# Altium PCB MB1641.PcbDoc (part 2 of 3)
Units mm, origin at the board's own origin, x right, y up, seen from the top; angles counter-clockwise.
Board outline 70 x 64.48 mm, 4 copper layers (Top Layer, GND, VCC, Bottom Layer), stack 1.502 mm thick; 161 components, 126 nets, 622 pads, 1092 vias.
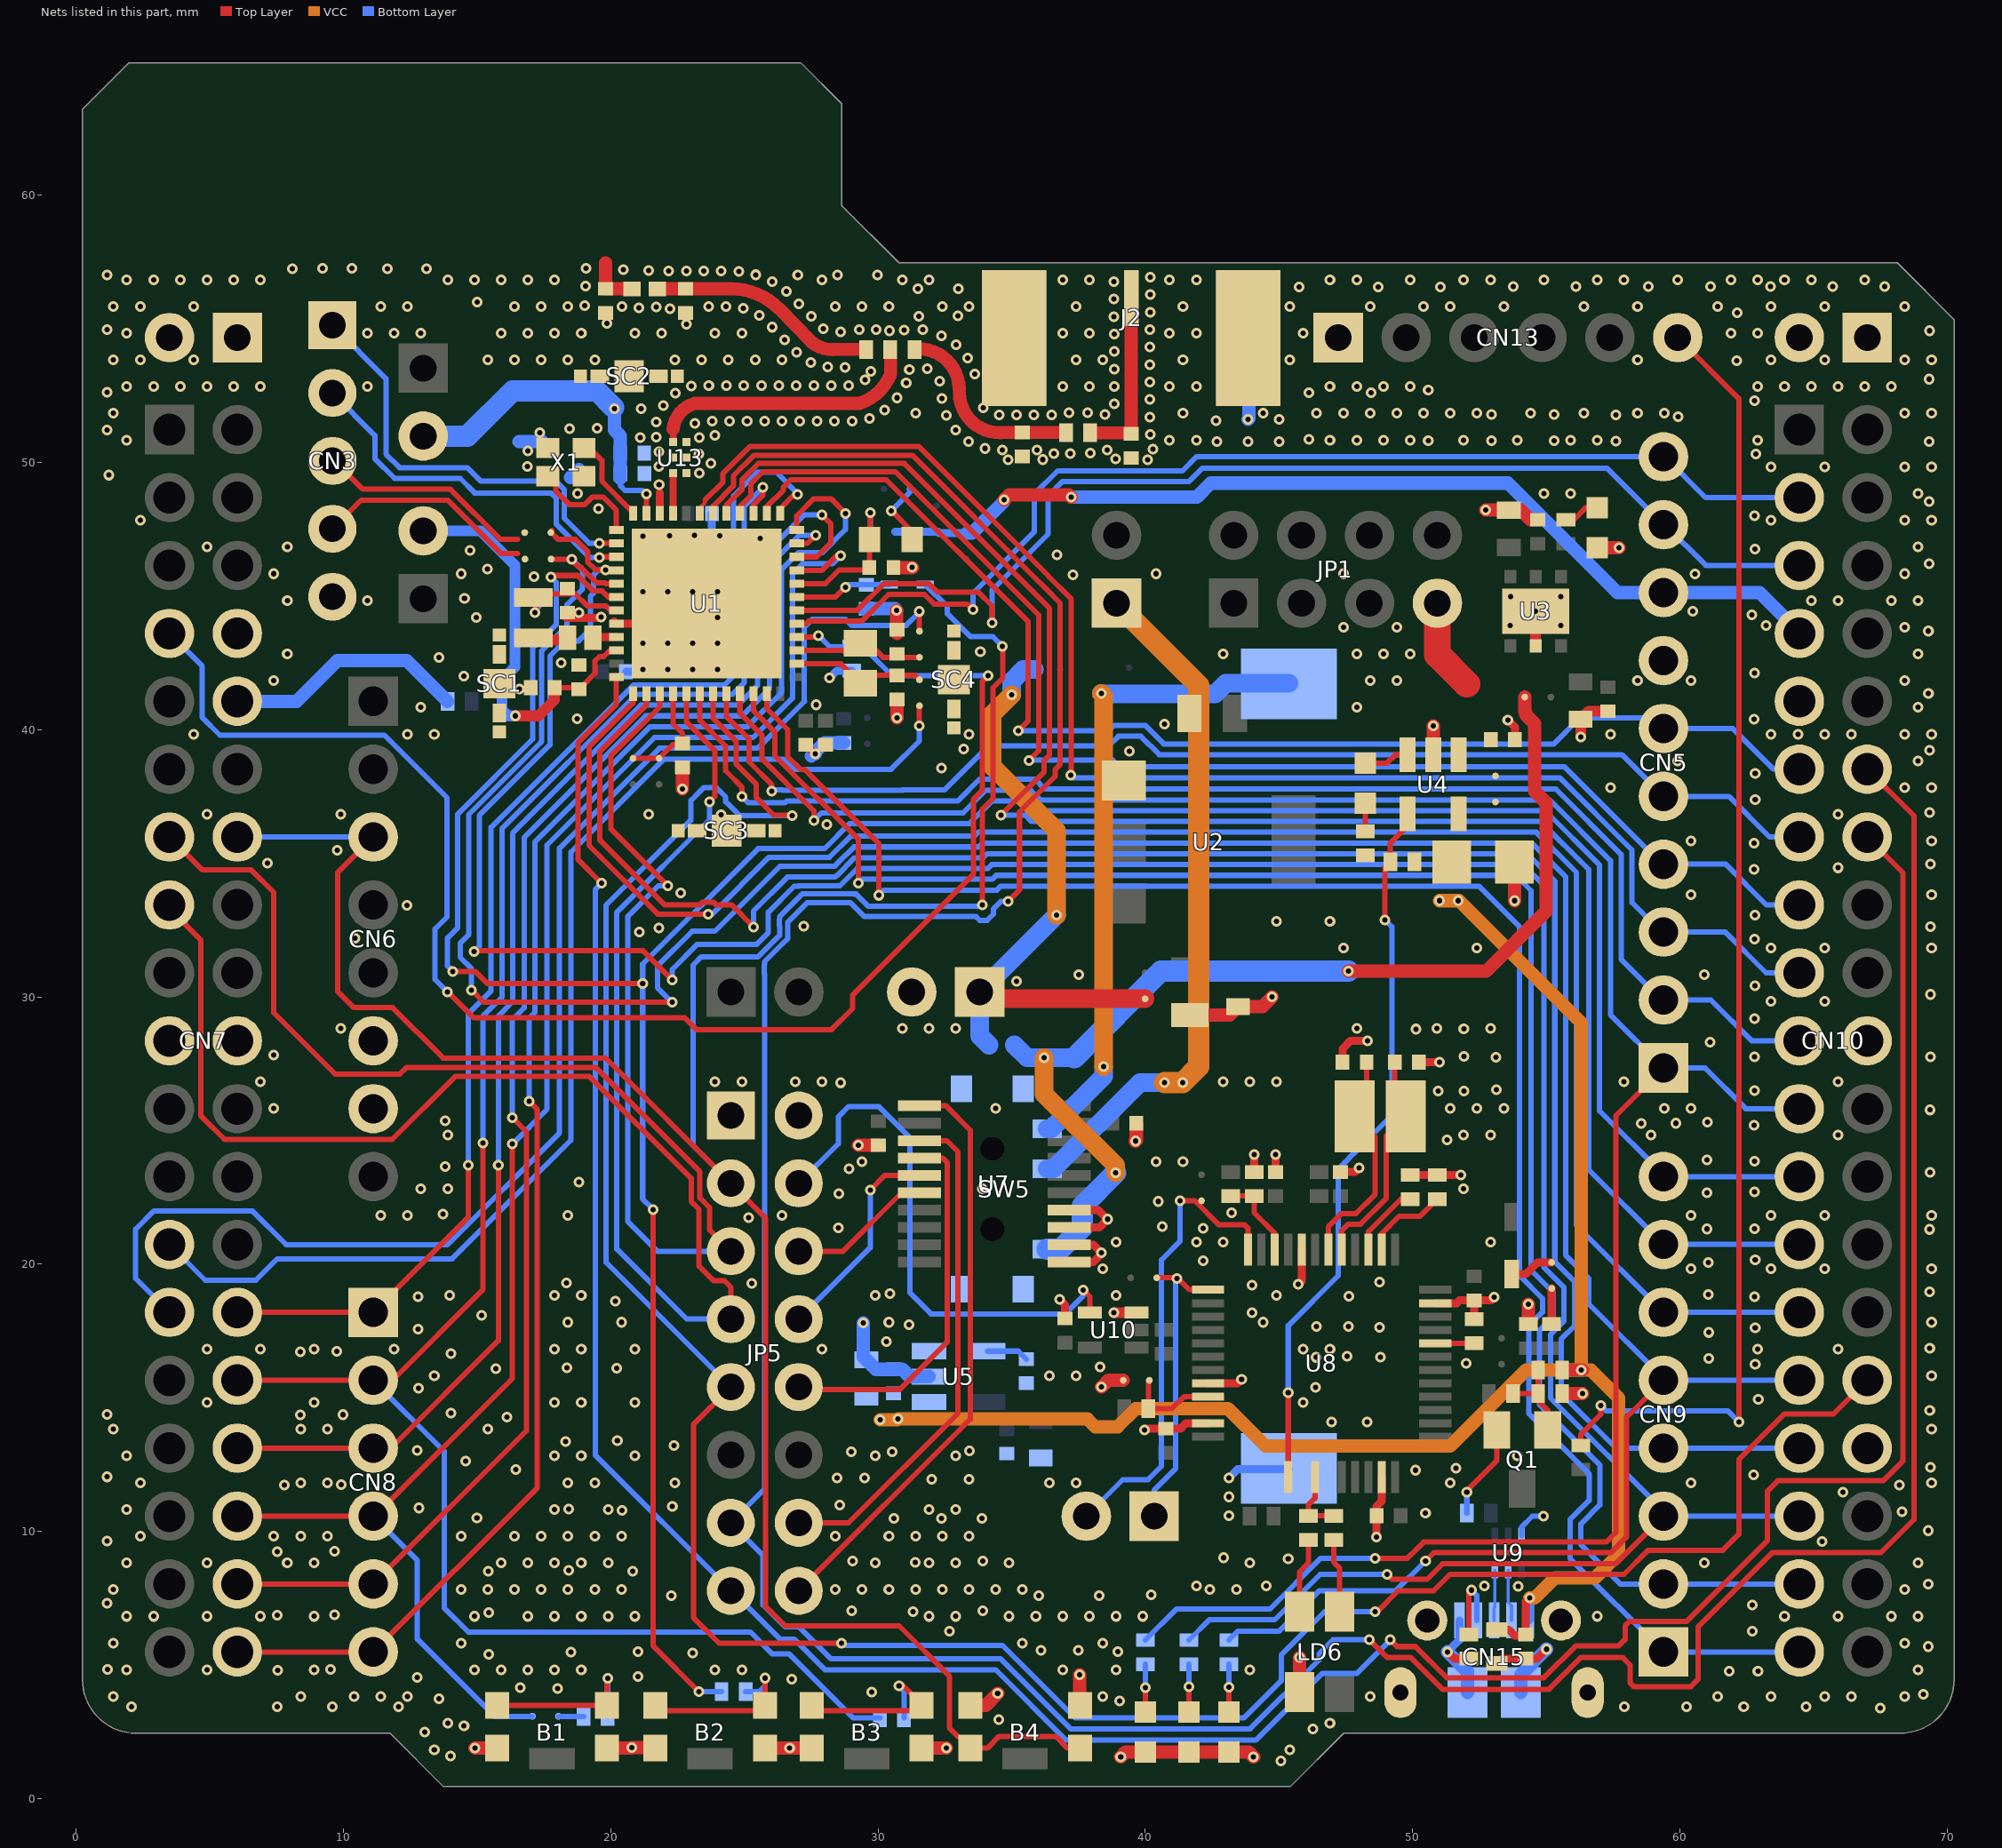
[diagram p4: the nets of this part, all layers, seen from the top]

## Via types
v1: diameter 0.4, hole 0.2, Top Layer to Bottom Layer, tented both sides, 1003 vias
v2: diameter 0.4/0.4/0.3/0.4 (per signal layer), hole 0.2, Top Layer to Bottom Layer, tented both sides, 89 vias

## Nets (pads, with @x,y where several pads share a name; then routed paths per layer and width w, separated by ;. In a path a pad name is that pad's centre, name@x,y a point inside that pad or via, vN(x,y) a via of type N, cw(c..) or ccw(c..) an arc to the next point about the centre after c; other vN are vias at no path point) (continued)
5V_USB_STLINK: C11.1 C21.2 C25.2 C51.1 CN15.1 R11.2 R12.2 R16.2 SB15.1 U4.5 U5.1 U5.3 U12.1 | length 64.5
  Top Layer w0.3: U12.1@53.15,6.325 53.6,6.325 53.825,6.1 54.18,6.1 C51.1@54.23,6.15 54.23,7.391 54.252,7.391 v1(54.381,7.521)
  Top Layer w0.5: R16.2@55.59,16.044 v1(56.3,16.044) v1@56.347,16.044
  VCC w0.5: v1(30.087,14.19) 30.733,14.19 v1(30.752,14.209) 37.834,14.209 38.12,13.923 38.967,13.923 39.644,14.6 43.095,14.6 44.495,13.2 51.4,13.2 54.244,16.044 v1(56.3,16.044) ; v1(51,33.6) v1(51.7,33.6) 51.733,33.6 56.3,29.033 v1(56.3,16.044) ; v1(54.381,7.521) 54.564,7.521 55.315,8.271 56.822,8.271 57.707,9.157 57.707,15 56.663,16.044 v1(56.3,16.044)
  Bottom Layer w0.3: CN15.1@54.345,6.675 54.381,6.711 v1(54.381,7.521)
AIN_1: R26.2 R28.2 U8.10 | length 3.2
  Top Layer w0.2: R26.2@43.2,22.55 R28.2@44.07,22.55 44.07,21.927 44.845,21.152 U8.10@44.845,20.544
ANT: C37.2 L1.2 | length 2
  Top Layer w0.49: 19.816,57.466 C37.2@19.816,56.488 L1.2@20.8,56.488
AT0: CN3.1 U1.26 | length 16.3
  Top Layer w0.2: v1@19.595,46.962 U1.26@20.214,46.962
  Bottom Layer w0.2: CN3.1@9.596,55.131 11.6,53.127 11.6,50.306 12.109,49.798 14.639,49.798 15.139,49.297 17.947,49.297 18.273,48.972 18.273,47.898 19.198,46.973 v1(19.583,46.973)
AT1: CN3.2 U1.27 | length 14.2
  Top Layer w0.2: v1@19.595,46.462 U1.27@20.214,46.462
  Bottom Layer w0.2: CN3.2@9.596,52.591 11.184,51.003 11.184,50.134 11.924,49.394 14.378,49.394 14.919,48.853 17.766,48.853 17.971,48.648 17.971,47.773 17.973,47.772 17.973,47.681 19.222,46.431 v1(19.583,46.431)
AT2: CN3.3 SB5.2 | length 8.1
  Top Layer w0.2: CN3.3@9.596,50.051 9.676,50.051 10.736,48.991 14.009,48.991 15.883,47.117 16.521,47.117
AT3: CN3.4 SB6.2 | length 8.2
  Top Layer w0.2: CN3.4@9.596,47.511 10.673,48.588 13.908,48.588 15.912,46.584 16.519,46.584
AVDD: CN5.8 CN10.7 SB25.1 SB26.1 SB27.1 | length 37
  Top Layer w0.5: v1(34.72,48.6) 34.894,48.774 37.146,48.774 v1(37.22,48.7)
  Bottom Layer w0.3: SB25.1@30.65,47.4 SB27.1@32.2,47.4 32.245,47.4 32.295,47.35 SB26.1@33.32,47.35
  Bottom Layer w0.5: SB26.1@33.32,47.35 33.525,47.35 v1@34.725,48.55 ; v1(37.22,48.7) 41.926,48.7 42.446,49.22 53.561,49.22 57.657,45.124 CN5.8@59.38,45.124 62.976,45.124 64.46,43.64 CN10.7@64.46,43.6
BOOT0: CN7.7 R6.2 U1.4 | length 60.1
  Top Layer w0.2: v1@13.91,30.19 14.874,29.226 22.768,29.226 23.216,28.778 28.266,28.778 29.058,29.57 29.058,30.074 33.579,34.595 33.579,37.401 33.9,37.722 33.9,41.796 v1(34.12,42.016) ; U1.4@26.964,43.462 27.699,43.462 v1@27.775,43.538
  Bottom Layer w0.2: CN7.7@3.5,43.6 4.73,42.37 4.73,40.45 5.39,39.79 11.542,39.79 13.88,37.452 13.88,32.99 13.43,32.54 13.43,30.654 v1(13.904,30.18) ; v1(27.775,43.516) 28.188,43.103 R6.2@29.018,43.103 29.44,43.103 30.528,42.016 v1(34.12,42.016)
GND: B1.1 B1.3 B2.1 B2.3 B3.1 B3.3 B4.2 B4.4 C3.1 C6.1 C7.1 C8.1 C9.2 C10.2 C11.2 C12.1 C13.1 C14.1 C15.1 C16.1 C17.1 C18.1 C19.1 C20.1 C21.1 C22.1 C23.1 C24.1 C25.1 C26.1 C27.1 C28.2 C29.1 C31.1 C32.1 C33.1 C34.1 C36.1 C37.1 C39.1 C40.1 C41.2 C42.1 C43.2 C44.2 C45.2 C46.1 C47.1 C48.1 C49.1 C50.1 C51.2 CN2.2 CN3.5 CN4.2 CN5.7 CN6.6 CN6.7 CN7.8 CN7.19 CN7.20 CN10.9 CN10.20 CN10.32 CN11.1 CN11.2 CN12.1 CN12.2 CN13.1 CN15.5 CN15.6 CN15.7 CN15.8 CN15.9 CN15.10 CN15.11 J2.2 J2.3 J2.4 J2.5 JP5.1 JP5.2 LD1.2 LD2.2 LD3.2 LD5.2 LD6.1 R6.1 R15.2 R18.2 R19.2 R20.1 R22.2 R23.1 R28.1 SB32.2 SC1.1 SC2.1 SC3.1 SC4.1 SW5.0 U1.22 U1.32 U1.49 U2.1 U3.2 U3.EP U4.2 U5.2 U7.11 U7.12 U7.13 U7.14 U8.8 U8.20 U8.23 U8.35 U8.47 U9.3 U10.3 U12.2 U13.A2 U13.B1 U13.B2 U13.B3 X1.2 X1.4 | length 90.3
  Top Layer w0.3: C29.1@18.351,44.175 v1@19.621,44.175 ; U1.32@20.132,44.044 U1.32@20.214,43.962 22.839,43.962 U1.49@23.589,44.712 ; U1.22@21.839,48.087 21.839,48.853 ; C20.1@27.289,39.435 C20.1@27.3,39.435 27.307,39.428 v1(27.649,39.085) ; v1(36.791,18.68) 37,18.471 C43.2@37,17.97 ; U7.11@37.152,20.075 38.045,20.075 38.379,20.409 v1(38.362,20.425) 38.062,20.725 U7.12@37.152,20.725 ; U7.13@37.152,21.375 38.275,21.375 v1(38.586,21.686) 38.246,22.025 U7.14@37.152,22.025 ; v1(39.97,13.8) 40.02,13.85 C48.1@40.77,13.85 41.32,13.85 41.514,14.044 U8.23@42.345,14.044 ; U8.20@42.345,15.544 43.444,15.544 v1(43.6,15.7) ; R28.1@44.07,23.45 v1(44.07,24.1) ; C50.1@44.87,23.45 v1(44.87,24.1) ; v1(45.72,19.247) 45.845,19.372 U8.8@45.845,20.544 ; C46.1@47.3,23.45 47.845,23.45 v1(47.995,23.6) ; C44.2@47.377,27.561 47.377,28.057 47.68,28.36 v1(48.314,28.36) ; v1@48.65,9.805 C47.1@48.65,10.591 48.65,10.95 48.845,11.145 U8.35@48.845,12.044 ; R22.2@49.913,23.337 R18.2@50.913,23.337 v1(51.801,23.337) ; C45.2@50.231,27.561 v1(50.998,27.561) ; U8.47@50.845,18.544 51.644,18.544 51.75,18.65 C49.1@52.3,18.65 ; v1(51.3,5.5) 51.55,5.25 R23.1@52.1,5.25 ; R19.2@52.294,17.95 52.3,17.956 C49.1@52.3,18.65 ; v1(53.05,18.769) 52.931,18.65 C49.1@52.3,18.65 ; U12.2@53.15,5.075 53.325,5.25 C51.2@54.23,5.25 54.65,5.25 v1(55,5.6) ; v1(53.554,40.362) 53.823,40.093 C12.1@53.823,39.629
  Top Layer w0.4: v1(38.83,18.19) U10.3@39.675,18.19 ; U3.2@54.6,43.13 v1(54.6,44.43) ; v1(56.28,39.72) C13.1@56.28,40.385 56.58,40.685 C16.1@57.296,40.685
  Top Layer w0.5: v1(14.931,1.9) B1.1@15.76,1.9 ; B1.3@19.86,1.9 20.78,1.9 v1(20.793,1.913) B2.1@21.622,1.913 ; v1(22.687,37.777) 22.687,38.581 C31.1@22.689,38.583 ; B2.3@25.773,1.9 v1(26.7,1.9) B3.1@27.528,1.9 ; v1(29.262,24.45) C42.1@30.012,24.45 ; C32.1@30.579,46.062 v1@31.288,46.062 ; v1(30.7,44.462) 30.7,43.612 C7.1@30.712,43.6 ; v1(30.712,40.441) C6.1@30.712,41.128 ; B3.3@31.629,1.9 v1(32.557,1.9) ; B4.2@33.454,3.3 B4.2@33.46,3.306 ; B4.2@33.454,3.5 34.035,3.5 v1(34.477,3.943) ; v1(37.55,4.638) 37.55,3.744 37.56,3.734 37.554,3.728 B4.4@37.554,3.5 ; v1(38.362,15.407) 38.615,15.66 SB32.2@39.175,15.66 ; C9.2@41.67,29.327 43.158,29.327 C8.1@43.47,29.639 44.384,29.639 v1(44.745,30) ; LD6.1@45.77,4 v1(45.77,5.3) ; U4.2@50.764,39.054 v1(50.764,40.136) ; v1(52.736,48.211) C15.1@53.6,48.211 54.039,48.211 54.4,47.85 C14.1@54.672,47.85 ; v1(53.805,33.6) C11.2@53.805,35.048 ; R15.2@54.326,17.759 v1(54.326,18.499) ; R20.1@55.59,15.159 v1(56.347,15.159) ; LD5.2@56.9,46.8 v1(57.717,46.8)
  Top Layer w0.508: v1(39.08,1.57) 39.26,1.75 LD1.2@40.004,1.75 LD2.2@41.631,1.75 LD3.2@43.124,1.75 43.868,1.75 v1(44.048,1.57) ; v1(39.63,24.61) 39.662,24.642 C41.2@39.662,25.275
  Bottom Layer w0.2: U9.3@54.074,9.85 54.074,10.174 54.476,10.576 v1(54.898,10.576)
  Bottom Layer w0.3: C18.1@20.586,42.164 21.128,42.164 v1(21.214,42.25) ; C19.1@23.789,48.087 23.789,47.31 v1@24.011,47.088 ; v1(28.192,41.928) 28.467,42.203 R6.1@29.018,42.203 ; v1(43.12,12) 43.454,12.334 CN2.2@45.37,12.334 ; v1(51.3,5.5) 51.745,5.945 CN15.5@51.745,6.675
  Bottom Layer w0.5: 16.578,50.775 17.45,50.775 ; 18.5,49.425 18.808,49.733 18.859,49.682 ; v1(27.649,39.085) 27.581,39.085 27.51,39.014 27.998,39.503 C28.2@28.718,39.503 ; C3.1@29.525,44.483 C3.1@29.562,44.521 30.641,44.521 v1(30.7,44.462) ; v1(43.845,51.6) 43.881,51.636 J2.5@43.881,54.86 ; v1(51.3,5.5) 52.045,4.755 CN15.11@52.045,3.975 ; CN15.10@54.045,3.975 54.045,4.645 v1(55,5.6)
  Bottom Layer w0.508: v1(29.452,17.799) 29.452,16.537 C21.1@29.562,16.427 29.917,16.072 C25.1@30.579,16.072 30.908,16.072 31.18,15.8 U5.2@31.91,15.8
  other v1: 45.068,1.417 14.015,1.61 13.407,1.83 45.407,1.83 13.052,2.507 46.271,2.622 14.52,2.738 13.907,2.83 46.907,2.83 34.512,2.96 67.493,3.391 7.531,3.441 9.594,3.441 57.909,3.441 60.243,3.441 62.378,3.441 64.712,3.441 2.084,3.45 12.063,3.45 39.035,3.658 13.587,3.74 1.407,3.83 8.407,3.83 10.407,3.83 11.407,3.83 12.407,3.83 38.407,3.83 48.407,3.83 61.407,3.83 63.407,3.83 65.407,3.83 66.407,3.83 68.407,3.83 69.1,3.918 29.77,3.993 18.02,4.128 16.616,4.164 26.78,4.472 12.772,4.551 21.03,4.58 61.842,4.77 62.91,4.77 7.55,4.81 1.186,4.839 1.907,4.83 4.907,4.83 8.907,4.83 14.907,4.83 15.907,4.83 16.907,4.83 17.907,4.83 18.907,4.83 23.907,4.83 24.907,4.83 36.907,4.83 38.907,4.83 43.907,4.83 68.907,4.83 9.52,4.851 15.442,5.408 23.075,5.458 18.52,5.489 21.02,5.513 38.973,5.505 36.09,5.556 37.5,5.556 69.278,5.7 1.407,5.83 14.407,5.83 35.407,5.83 38.407,5.83 68.407,5.83 32.668,6.268 62.7,6.27 1.907,6.83 2.907,6.83 4.907,6.83 6.907,6.83 8.907,6.83 14.907,6.83 16.907,6.83 17.907,6.83 18.907,6.83 19.907,6.83 20.907,6.83 31.907,6.83 32.907,6.83 34.907,6.83 35.907,6.83 36.907,6.83 37.907,6.83 38.907,6.83 39.907,6.83 56.907,6.83 63.907,6.83 65.907,6.83 67.907,6.83 68.907,6.83 7.531,6.868 9.669,6.888 15.438,6.966 31.314,7 29.018,7.036 33.923,7.037 62.7,7.25 1.166,7.32 22.275,7.605 36.02,7.605 38.275,7.605 40.213,7.634 1.407,7.83 14.407,7.83 15.407,7.83 16.407,7.83 17.407,7.83 18.407,7.83 19.407,7.83 20.407,7.83 28.407,7.83 29.407,7.83 30.407,7.83 31.407,7.83 32.407,7.83 33.407,7.83 34.407,7.83 35.407,7.83 42.407,7.83 43.407,7.83 68.407,7.83 41.912,7.964 44.522,7.964 53.947,7.947 52.686,7.972 69.278,8.034 15.418,8.512 20.826,8.512 18.439,8.55 1.907,8.83 4.907,8.83 7.907,8.83 8.907,8.83 15.907,8.83 16.907,8.83 17.907,8.83 18.907,8.83 19.907,8.83 29.907,8.83 31.4,8.844 31.907,8.83 32.907,8.83 34.907,8.83 43.907,8.83 60.907,8.83 68.907,8.83 29.055,8.895 33.917,8.895 45.345,8.981 42.925,9.023 7.531,9.245 9.669,9.266 65.303,9.63 1.166,9.654 48.65,9.8 2.407,9.83 7.407,9.83 8.407,9.83 9.407,9.83 14.407,9.83 16.407,9.83 17.407,9.83 18.407,9.83 19.407,9.83 20.407,9.83 28.407,9.83 30.407,9.83 31.407,9.83 32.407,9.83 33.407,9.83 69.278,10.037 30.6,10.5 32.371,10.5 33.886,10.5 15.002,10.513 43.12,10.6 50.479,10.686 68.301,10.744 20.428,10.797 1.907,10.83 17.907,10.83 19.907,10.83 31.907,10.83 32.907,10.83 18.439,10.836 12.84,10.884 22.313,10.946 28.576,10.995 43.12,11.3 66.091,11.481 7.791,11.744 68.199,11.735 9.929,11.764 2.407,11.83 8.407,11.83 9.407,11.83 18.407,11.83 19.407,11.83 22.407,11.83 36.407,11.83 37.407,11.83 51.407,11.83 60.407,11.83 69.407,11.83 32.012,11.958 33.406,11.958 28.463,12 29.493,12 1.166,12.048 62.75,12.12 50.108,12.297 16.45,12.328 51.617,12.371 69.36,12.4 14.579,12.636 1.907,12.83 17.907,12.83 18.907,12.83 20.907,12.83 29.907,12.83 32.907,12.83 53.907,12.83 29,12.983 30.528,12.983 12.772,13.039 33.418,13.027 22.375,13.219 18.32,13.37 20.253,13.399 1.407,13.83 8.407,13.83 9.407,13.83 15.407,13.83 69.407,13.83 46.96,14.1 48.3,14.1 16.12,14.287 8.397,14.358 1.166,14.382 9.992,14.374 14.023,14.427 69.34,14.526 4.907,14.83 8.907,14.83 17.907,14.83 18.907,14.83 20.907,14.83 45.907,14.83 62.926,14.946 12.821,15.363 46.365,15.391 13.407,15.83 36.407,15.83 37.407,15.83 69.407,15.83 15.702,16.092 20.234,16.109 18.364,16.129 38.311,16.154 62.81,16.257 51.994,16.296 61.073,16.468 46.384,16.518 48.787,16.531 47.553,16.566 14.034,16.663 8.394,16.723 9.752,16.747 4.907,16.83 6.907,16.83 8.907,16.83 11.907,16.83 17.907,16.83 18.907,16.83 20.907,16.83 27.907,16.83 45.907,16.83 46.907,16.83 62.907,16.83 65.907,16.83 69.34,16.86 30.319,17.1 61.073,17.448 12.801,17.569 48.767,17.636 62.81,17.62 46.404,17.675 47.6,17.672 31.162,17.737 18.407,17.83 20.407,17.83 30.407,17.83 44.407,17.83 69.407,17.83 15.171,18.09 43.998,18.193 20.182,18.621 62.787,18.78 12.801,18.793 47.62,18.806 13.973,18.832 17.907,18.83 18.907,18.83 29.907,18.83 38.907,18.83 44.907,18.83 61.06,18.862 30.449,18.898 69.33,18.97 43.998,19.223 25.273,19.279 18.345,19.299 48.753,19.334 38.407,19.83 60.407,19.83 63.407,19.83 65.407,19.83 69.407,19.83 61.06,20.063 42.166,20.125 62.81,20.161 38.907,20.83 41.907,20.83 42.907,20.83 52.907,20.83 61.011,21.32 69.33,21.304 42.166,21.344 62.787,21.33 28.52,21.356 40.632,21.419 25.157,21.739 11.407,21.83 12.407,21.83 18.407,21.83 26.407,21.83 60.407,21.83 63.407,21.83 65.407,21.83 69.407,21.83 13.735,21.874 43.231,21.927 40.48,22.35 28.532,22.634 61,22.678 62.787,22.701 12.907,22.83 13.907,22.83 33.907,22.83 51.907,22.83 18.809,23.075 69.35,23.44 28.924,23.575 13.807,23.658 29.407,23.83 40.407,23.83 41.407,23.83 62.78,23.86 61.014,23.91 51.289,24.656 13.907,24.83 51.907,24.83 52.907,24.83 58.907,24.83 65.907,24.83 62.77,25.207 58.55,25.26 59.849,25.275 61.03,25.31 13.82,25.363 69.35,25.774 7.407,25.83 34.407,25.83 51.407,25.83 52.407,25.83 53.407,25.83 59.407,25.83 60.407,25.83 50.961,26.486 51.92,26.486 62.787,26.49 53.137,26.522 28.6,26.788 6.907,26.83 23.907,26.83 24.907,26.83 26.907,26.83 27.907,26.83 42.907,26.83 43.907,26.83 44.907,26.83 57.907,26.83 65.907,26.83 53.118,27.749 51.92,27.773 62.787,27.76 69.36,27.76 7.407,27.83 61.13,28.3 50.122,28.797 51.909,28.813 9.907,28.83 30.907,28.83 31.907,28.83 32.907,28.83 47.907,28.83 50.907,28.83 52.907,28.83 62.79,29.19 63.407,29.83 65.407,29.83 69.36,30.094 62.8,30.417 35.176,30.589 37.51,30.838 60.907,30.83 47.407,31.83 52.407,31.83 63.407,31.83 65.407,31.83 69.407,31.83 62.787,32.17 10.434,32.19 21.077,32.422 21.8,32.571 27.229,32.639 69.36,32.63 44.907,32.83 46.907,32.83 62.804,33.06 12.381,33.426 60.407,33.83 69.407,33.83 22.62,33.889 62.767,34.77 65.907,34.83 69.36,34.964 7.163,35.001 9.779,35.484 62.767,35.75 60.407,35.83 69.407,35.83 28.088,36.448 24.138,36.818 4.907,36.83 9.907,36.83 21.425,36.83 65.907,36.83 69.33,36.892 62.81,37.387 57.407,37.83 68.407,37.83 69.407,37.83 62.81,38.367 32.371,38.554 59.907,38.83 68.907,38.83 39.406,39.188 69.33,39.226 33.2,39.276 4.407,39.83 12.407,39.83 13.407,39.83 33.407,39.83 57.407,39.83 63.407,39.83 64.407,39.83 65.407,39.83 66.407,39.83 68.407,39.83 69.407,39.83 40.714,40.202 18.745,40.399 62.773,40.381 12.907,40.83 47.907,40.83 68.907,40.83 27.683,40.928 69.29,41.353 16.586,41.52 7.407,41.83 48.407,41.83 49.407,41.83 58.407,41.83 60.407,41.83 68.407,41.83 14.515,42 62.787,42.12 22.139,42.25 23.075,42.25 24,42.25 18.144,42.5 13.587,42.691 7.907,42.83 42.907,42.83 47.907,42.83 48.907,42.83 49.907,42.83 68.907,42.83 33.829,42.907 21.214,43.229 22.139,43.229 23.075,43.229 24,43.229 69.29,43.687 47.407,43.83 49.407,43.83 68.407,43.83 53.65,43.9 55.548,43.9 63.218,43.888 14.982,44.187 19.653,44.208 24,44.186 62.685,44.294 18.809,44.381 60.48,44.433 7.907,44.83 10.907,44.83 64.907,44.83 65.907,44.83 67.907,44.83 68.907,44.83 14.536,44.903 53.665,44.971 55.545,44.971 21.214,45.161 22.139,45.161 23.075,45.161 24,45.161 17.131,45.721 37.29,45.792 7.407,45.83 14.407,45.83 40.407,45.83 47.407,45.83 60.551,45.818 68.407,45.83 15.39,46 31.279,46.074 69.32,46.2 36.693,46.536 14.738,46.71 62.8,46.76 4.907,46.83 7.907,46.83 68.907,46.83 25.603,47.153 21.214,47.23 22.205,47.244 24.079,47.244 23.135,47.264 2.407,47.83 63.407,47.83 68.407,47.83 69.407,47.83 62.787,48 19.552,48.264 69.32,48.534 18.764,48.827 54.907,48.83 55.907,48.83 68.907,48.83 21.815,49.161 1.242,49.52 23.323,49.589 63.407,49.83 65.407,49.83 68.407,49.83 69.407,49.83 16.891,49.85 21.81,49.85 23.758,49.958 34.867,50.096 36.167,50.101 40.081,50.089 38.891,50.122 23.3,50.306 36.58,50.321 37.188,50.327 62.83,50.31 37.941,50.345 21.8,50.39 16.907,50.419 40.284,50.485 42.675,50.775 43.839,50.775 45,50.775 69.32,50.775 50.58,50.81 52.954,50.8 55.288,50.8 57.596,50.795 1.907,50.83 40.907,50.83 41.907,50.83 46.907,50.83 47.907,50.83 48.907,50.83 49.907,50.83 51.907,50.83 53.907,50.83 55.907,50.83 56.907,50.83 62.907,50.83 46.119,50.86 21.104,50.92 23.317,50.927 21.714,50.943 23.899,51.01 17.348,51.105 1.166,51.201 18.465,51.257 19.497,51.271 42.65,51.562 45,51.6 59.926,51.704 57.596,51.775 38.495,51.79 52.954,51.78 55.288,51.78 1.407,51.83 31.407,51.83 41.407,51.83 44.407,51.83 46.407,51.83 47.407,51.83 48.407,51.83 49.407,51.83 50.407,51.83 51.407,51.83 52.407,51.83 54.407,51.83 56.407,51.83 58.407,51.83 59.407,51.83 68.407,51.83 69.407,51.83 37.838,51.854 37.141,51.857 21.148,52.01 62.787,52.3 46.11,52.605 48.444,52.605 1.166,52.626 50.58,52.7 1.907,52.83 2.907,52.83 3.907,52.83 4.907,52.83 5.907,52.83 6.907,52.83 10.907,52.83 36.907,52.83 37.907,52.83 40.907,52.83 41.907,52.83 46.907,52.83 47.907,52.83 48.907,52.83 49.907,52.83 62.907,52.83 63.907,52.83 64.907,52.83 65.907,52.83 66.907,52.83 67.907,52.83 69.32,53.109 29.73,53.393 31.171,53.459 62.115,53.8 1.407,53.83 2.407,53.83 4.407,53.83 15.407,53.83 16.407,53.83 17.407,53.83 18.407,53.83 19.407,53.83 22.407,53.83 23.407,53.83 24.407,53.83 25.407,53.83 26.407,53.83 37.407,53.83 38.407,53.83 41.407,53.83 45.407,53.83 58.407,53.83 63.407,53.83 65.407,53.83 68.407,53.83 69.407,53.83 1.907,54.83 10.907,54.83 11.907,54.83 12.907,54.83 15.907,54.83 16.907,54.83 17.907,54.83 18.907,54.83 20.907,54.83 21.907,54.83 23.907,54.83 24.907,54.83 36.907,54.83 37.907,54.83 40.907,54.83 41.907,54.83 45.907,54.83 61.907,54.83 62.907,54.83 30.429,54.92 69.33,54.92 30.984,54.95 1.166,54.96 29.297,54.964 29.925,54.958 31.683,54.958 22.83,55.169 19.863,55.194 31.525,55.457 32.995,55.471 62.14,55.6 22.225,55.744 21.057,55.778 1.407,55.83 2.407,55.83 4.407,55.83 11.407,55.83 12.407,55.83 16.407,55.83 17.407,55.83 18.407,55.83 20.422,55.829 28.407,55.83 29.407,55.83 30.407,55.83 32.407,55.83 33.407,55.83 37.407,55.83 41.407,55.83 45.407,55.83 48.407,55.83 50.407,55.83 51.407,55.83 53.407,55.83 56.407,55.83 58.407,55.83 61.407,55.83 63.407,55.83 65.407,55.83 68.407,55.83 19.025,55.855 15.008,55.997 31.5,56.488 33.001,56.488 45.75,56.55 48.706,56.56 51.04,56.56 53.766,56.57 56.1,56.57 58.806,56.58 61.14,56.58 63.376,56.58 65.71,56.58 67.66,56.58 19.072,56.591 1.907,56.83 2.907,56.83 3.907,56.83 4.907,56.83 5.907,56.83 6.907,56.83 13.907,56.83 14.907,56.83 15.907,56.83 16.907,56.83 17.907,56.83 27.907,56.83 30.907,56.83 31.907,56.83 36.907,56.83 37.907,56.83 40.907,56.83 41.907,56.83 46.907,56.83 47.907,56.83 49.907,56.83 51.907,56.83 52.907,56.83 54.907,56.83 56.907,56.83 57.907,56.83 59.907,56.83 61.907,56.83 62.907,56.83 63.907,56.83 64.907,56.83 66.907,56.83 1.166,57.01 27,57 28.48,57 29.98,57 20.472,57.201 8.097,57.231 11.661,57.232 13.11,57.232 9.233,57.256 10.32,57.256 19.08,57.252
  other v2: 34.647,50.451 35.955,50.451 38.578,50.451 33.997,50.516 33.395,50.773 40.188,51.038 32.904,51.205 23.148,51.459 21.71,51.512 23.797,51.537 24.451,51.537 25.105,51.537 25.759,51.537 26.413,51.537 27.067,51.537 27.721,51.537 28.375,51.537 29.029,51.537 29.676,51.632 40.163,51.691 32.556,51.758 34.529,51.77 35.183,51.777 35.837,51.777 36.491,51.777 30.245,51.954 33.933,52.041 21.967,52.113 38.837,52.179 40.163,52.345 30.713,52.411 32.398,52.393 22.426,52.579 38.837,52.833 23.022,52.849 23.676,52.863 24.33,52.863 24.984,52.863 25.638,52.863 26.292,52.863 26.946,52.863 27.6,52.863 28.254,52.863 28.908,52.863 31.055,52.969 40.163,52.999 32.309,53.041 29.524,53.08 33.621,53.301 31.849,53.506 38.837,53.487 28.777,53.556 28.123,53.563 40.163,53.653 27.492,53.734 33.361,53.902 26.962,54.117 38.837,54.141 40.163,54.307 32.926,54.389 26.505,54.585 32.369,54.732 38.837,54.795 28.605,54.882 40.165,54.961 27.961,54.998 26.048,55.053 27.501,55.463 38.817,55.449 25.566,55.495 40.183,55.615 24.968,55.761 21.702,55.805 23.663,55.825 24.317,55.825 27.044,55.931 38.817,56.103 40.183,56.269 26.574,56.385 38.817,56.757 26.037,56.759 40.183,56.923 25.435,57.013 24.792,57.133 22.176,57.151 22.83,57.151 23.484,57.151 24.138,57.151 21.425,57.171
LED_STLK: R25.1 R27.1 U8.30 | length 2.5
  Top Layer w0.2: U8.30@46.345,12.044 46.345,11.245 46.095,10.995 R25.1@46.095,10.588 R27.1@47.045,10.588
NetB1_2: B1.2 B1.4 R7.1 | length 6.5
  Top Layer w0.2: B1.2@15.76,3.5 B1.4@19.86,3.5 19.86,4.47 v1(19.9,4.51)
  Bottom Layer w0.2: R7.1@19.9,3.1 v1(19.9,4.51)
NetB2_2: B2.2 B2.4 R8.1 | length 6.4
  Top Layer w0.2: B2.2@21.672,3.3 25.773,3.3 25.785,3.313 25.78,3.318 v1(25.78,4.52)
  Bottom Layer w0.2: R8.1@25.05,4.012 25.548,4.012 25.78,4.245 v1(25.78,4.52)
NetB3_2: B3.2 B3.4 R9.1 | length 6.8
  Top Layer w0.2: B3.2@27.528,3.3 31.622,3.3 31.75,3.429 30.954,4.225 v1(30.788,4.225)
  Bottom Layer w0.2: v1(30.788,4.225) 30.976,4.037 R9.1@30.976,3.029
NetC3_2: C3.2 D1.1 U1.7 | length 3.6
  Top Layer w0.2: U1.7@26.964,44.962 28.41,44.962 v1@28.776,45.327
  Bottom Layer w0.2: v1(28.787,45.316) 28.892,45.421 C3.2@29.562,45.421 D1.1@30.419,45.421
NetC6_2: C6.2 SB10.2 U1.2 X2.1 | length 5.1
  Top Layer w0.2: U1.2@26.964,42.462 28.614,42.462 X2.1@29.347,41.729 29.646,42.028 C6.2@30.712,42.028 31.39,42.028 SB10.2@31.552,41.866
NetC7_2: C7.2 SB12.2 U1.3 X2.2 | length 4.9
  Top Layer w0.2: U1.3@26.964,42.962 29.08,42.962 X2.2@29.347,43.229 29.658,43.229 30.187,42.7 30.712,42.7 31.548,42.7 SB12.2@31.552,42.704
NetC12_2: C12.2 JP1.7 SB15.2 U4.1 | length 3.5
  Top Layer w1: JP1.7@50.923,44.73 50.923,42.802 52.025,41.7
NetC23_2: C23.2 C24.2 JP6.2 SB23.2 U1.34 | length 15.5
  Top Layer w0.2: C23.2@17.914,41.563 18.532,41.563 18.611,41.641 18.952,41.641 19.411,42.1 19.411,42.563 19.579,42.731 19.744,42.731 19.975,42.962 U1.34@20.214,42.962
  Top Layer w0.4: v1(16.434,40.513) 17.303,40.513 17.326,40.536 ; 17.326,40.536 17.905,41.115 17.905,41.554 C23.2@17.914,41.563
  Bottom Layer w0.4: JP6.2@12.992,47.434 15.137,47.434 16.425,46.146 SB23.2@16.425,44.971 16.425,42.34 15.933,41.848 15.933,40.755 16.175,40.513 v1(16.434,40.513)
NetC26_2: C26.2 U5.4 | length 1.6
  Bottom Layer w0.2: U5.4@34.11,16.75 35.249,16.75 C26.2@35.549,16.45
NetC29_2: C29.2 L4.1 SB23.1 U1.31 | length 4.6
  Top Layer w0.2: v1(17.174,44.378) 17.174,44.454 17.224,44.504 17.224,44.982 17.317,45.075 18.683,45.075 19.139,44.619 19.821,44.619 19.978,44.462 U1.31@20.214,44.462
  Bottom Layer w0.2: v1(17.174,44.378) 17.174,44.454 17.4,44.68 SB23.1@17.4,44.971
NetC31_2: C31.2 SB21.2 SB22.2 U1.40 | length 4.1
  Top Layer w0.2: SB21.2@20.839,38.925 SB22.2@21.81,38.925 22.322,39.437 22.609,39.437 22.672,39.5 C31.2@22.689,39.483 22.689,39.855 22.339,40.205 U1.40@22.339,41.337
NetC32_2: C32.2 L6.2 SB25.2 U1.8 | length 5.8
  Top Layer w0.2: U1.8@26.964,45.462 28.039,45.462 28.55,45.973 29.59,45.973 C32.2@29.679,46.062 L6.2@29.679,47.114 29.712,47.147 v1(29.712,48.113)
  Bottom Layer w0.2: SB25.2@29.675,47.4 29.712,47.437 v1(29.712,48.113)
NetC33_2: C33.2 C34.2 JP4.2 U1.23 | length 12.9
  Top Layer w0.2: U1.23@21.339,48.087 v1(21.339,48.806)
  Bottom Layer w0.2: C33.2@20.364,49.403 20.364,49.124 20.542,48.946 21.199,48.946 v1(21.339,48.806)
  Bottom Layer w0.5: v1(20.142,52.01) 20.142,51.205 20.36,50.988 C34.2@20.36,50.343 20.36,49.407 C33.2@20.364,49.403
  Bottom Layer w0.8: JP4.2@12.992,50.979 14.644,50.979 16.335,52.67 19.494,52.67 v1@20.116,52.048
NetC36_2: C36.2 L1.1 R1.2 | length 8.5
  Top Layer w0.49: L1.1@21.75,56.488 C36.2@22.8,56.488 24.504,56.488 cw(c24.504,53.948) 26.3,55.744 27.495,54.52 ; 27.514,54.491 27.524,54.483 ; 27.527,54.486 ccw(c28.293,55.429) 28.309,54.215 ; 28.293,54.219 R1.2@29.493,54.219
NetC39_2: C39.2 R5.2 R13.1 | length 7.1
  Top Layer w0.49: R5.2@31.507,54.238 cw(c31.535,52.736) 33.037,52.753 ; 33.045,52.59 ccw(c34.548,52.607) 34.576,51.105 ; 34.62,51.114 C39.2@35.4,51.114 R13.1@36.979,51.114
NetC40_2: C40.2 J2.1 R13.2 | length 6.4
  Top Layer w0.49: R13.2@38.044,51.1 39.433,51.1 C40.2@39.473,51.06 ; C40.2@39.473,51.199 J2.1@39.473,56.146
NetC44_1: C44.1 U8.6 X3.1 | length 8.6
  Top Layer w0.2: U8.6@46.845,20.544 46.845,21.4 47.345,21.9 47.879,21.9 48.6,22.621 48.6,24.764 X3.1@47.835,25.529 48.277,25.971 C44.1@48.277,27.561
NetC45_1: C45.1 U8.5 X3.2 | length 8.4
  Top Layer w0.2: U8.5@47.345,20.544 47.345,21.259 47.583,21.497 48.046,21.497 49.003,22.454 49.003,24.797 X3.2@49.735,25.529 49.331,25.933 C45.1@49.331,27.561
NetCN2_1: CN2.1 SB19.1 SW5.3 | length 24.5
  VCC w0.7: v1(38.362,41.353) 38.446,41.269 v1(38.446,27.4)
  Bottom Layer w0.7: SW5.3@36.327,25.065 36.485,25.065 38.446,27.026 v1(38.446,27.4) ; v1(38.362,41.353) 38.379,41.337 SB19.1@39.39,41.337 42.607,41.337 43.004,41.734 CN2.1@45.37,41.734
NetCN4_1: CN4.1 SB13.1 SB16.1 SB17.1 | length 23.6
  Top Layer w0.7: CN4.1@33.802,30.183 34.055,29.93 SB13.1@39.99,29.93
  VCC w0.7: v1(35,41.304) 34.27,40.574 34.27,38.63 36.68,36.22 v1(36.68,33.061)
  Bottom Layer w0.7: SB16.1@34.15,28.2 33.802,28.548 CN4.1@33.802,30.183 v1(36.68,33.061) ; v1(35,41.304) 35,41.808 35.435,42.243 SB17.1@35.845,42.243
NetCN7_10: CN7.10 R33.1 | length 9.1
  Bottom Layer w0.5: CN7.10@6.04,41.06 8.26,41.06 9.784,42.584 12.376,42.584 R33.1@13.9,41.06
NetCN13_6: CN13.6 R31.1 | length 48.7
  Top Layer w0.2: R31.1@56.28,13.219 56.28,13.632 57.03,14.382 v1(57.03,14.72) ; CN13.6@59.914,54.664 62.2,52.378 v1(62.2,14.1)
  Bottom Layer w0.2: v1(57.03,14.72) 57.242,14.508 61.792,14.508 v1(62.2,14.1)
NetCN14_1: CN14.1 SB31.2 U8.13 | length 11.3
  Top Layer w0.2: SB31.2@40.425,19.494 41.198,19.494 41.648,19.044 U8.13@42.345,19.044
  Bottom Layer w0.2: CN14.1@40.33,10.576 40.33,11.55 41.14,12.36 41.14,19.42 v1(41.18,19.46)
NetCN14_2: CN14.2 SB30.2 U8.12 | length 17.6
  Top Layer w0.2: v1(41.305,22.375) 41.85,22.375 42.742,21.483 43.702,21.483 43.845,21.34 U8.12@43.845,20.544
  Bottom Layer w0.2: CN14.2@37.79,10.576 39.154,11.94 40.1,11.94 40.6,12.44 40.6,20.16 41.305,20.865 v1(41.305,22.375)
NetCN15_2: CN15.2 U9.5 | length 1.9
  Bottom Layer w0.12: U9.5@53.574,8.55 53.574,7.349 53.695,7.228 CN15.2@53.695,6.675
NetCN15_3: CN15.3 U9.6 | length 1.9
  Bottom Layer w0.12: CN15.3@53.045,6.675 53.045,7.145 53.074,7.174 U9.6@53.074,8.55
NetCN15_4: CN15.4 R23.2 | length 2.9
  Top Layer w0.2: R23.2@52.1,6.15 52.1,7.74 52.17,7.81 v1(52.2,7.81)
  Bottom Layer w0.2: v1(52.2,7.81) 52.395,7.615 CN15.4@52.395,6.675
NetD2_2: D2.2 SB28.1 | length 1.7
  Top Layer w0.3: D2.2@53.7,19.63 54.23,19.63 54.669,20.069 SB28.1@55.198,20.069
NetJP2_1: JP2.1 SW5.2 | length 26.6
  VCC w0.8: JP2.1@38.925,44.73 42,41.655 42,27.4 v1(41.4,26.8) v1(40.714,26.8)
  Bottom Layer w0.7: SW5.2@36.327,23.565 36.565,23.565 39.8,26.8 v1(40.714,26.8) v1(41.4,26.8)
NetJP5_4: JP5.4 U10.4 | length 20.5
  Top Layer w0.2: v1(37.68,19.034) 37.925,18.789 U10.4@37.925,18.19
  Bottom Layer w0.2: JP5.4@27.037,23.027 28.512,24.502 28.512,25.512 28.903,25.903 30.025,25.903 31.2,24.728 31.2,18.93 31.985,18.145 37.002,18.145 37.68,18.824 v1(37.68,19.034)
NetJP5_6: JP5.6 U7.6 | length 5.4
  Top Layer w0.2: JP5.6@27.037,20.487 28.693,20.487 30.881,22.675 U7.6@31.552,22.675
NetJP5_8: JP5.8 U7.5 | length 8
  Top Layer w0.2: v1(29.712,22.775) 30.262,23.325 U7.5@31.552,23.325
  Bottom Layer w0.2: JP5.8@27.037,17.947 29.712,20.622 v1(29.712,22.775)
NetJP5_10: JP5.10 U7.4 | length 14.1
  Top Layer w0.2: JP5.10@27.037,15.31 30.81,15.31 32.594,17.094 32.594,23.8 32.419,23.975 U7.4@31.552,23.975
NetJP5_14: JP5.14 U7.3 | length 19.1
  Top Layer w0.2: JP5.14@27.037,10.327 28.897,10.327 32.997,14.427 32.997,24.203 32.575,24.625 U7.3@31.552,24.625
NetJP5_16: JP5.16 U7.1 | length 22.2
  Top Layer w0.2: JP5.16@27.037,7.787 33.454,14.204 33.454,25.015 32.544,25.925 U7.1@31.552,25.925
NetL4_2: L4.2 L5.1 | length 1.2
  Top Layer w0.4: L4.2@17.224,43.482 17.351,43.354 L5.1@18.386,43.354
NetL5_2: L5.2 U1.33 | length 0.9
  Top Layer w0.3: L5.2@19.336,43.354 19.444,43.462 U1.33@20.214,43.462
NetL6_1: L6.1 SB24.2 | length 2.5
  Top Layer w0.2: v1(30.5,48.188) 31.279,47.409 L6.1@31.279,47.114
  Bottom Layer w0.2: v1(30.5,48.188) 31.2,48.888 SB24.2@31.2,49
NetLD1_1: LD1.1 R2.2 | length 1.8
  Top Layer w0.2: LD1.1@40.004,3.25 v1(40.004,4.161)
  Bottom Layer w0.2: R2.2@40,5.039 40.004,5.035 v1(40.004,4.161)
NetLD2_1: LD2.1 R3.2 | length 1.8
  Top Layer w0.2: LD2.1@41.631,3.278 v1(41.631,4.189)
  Bottom Layer w0.2: v1(41.631,4.189) R3.2@41.631,5.039
NetLD3_1: LD3.1 R4.2 | length 1.8
  Top Layer w0.2: LD3.1@43.124,3.261 v1(43.124,4.172)
  Bottom Layer w0.2: v1(43.124,4.172) R4.2@43.124,5.039
NetLD4_1: LD4.1 R12.1 | length 1.1
  Top Layer w0.2: R12.1@48.224,36.198 LD4.1@48.224,37.248
NetLD4_2: LD4.2 U4.3 | length 1.7
  Top Layer w0.2: LD4.2@48.224,38.748 49.04,38.748 49.346,39.054 U4.3@49.814,39.054
NetLD5_1: LD5.1 R10.1 | length 1.4
  Top Layer w0.2: R10.1@55.73,47.85 56.025,47.85 56.475,48.3 LD5.1@56.9,48.3
NetLD6_2: LD6.2 R25.2 | length 2.8
  Top Layer w0.2: LD6.2@45.77,7 45.77,8.5 46.095,8.825 R25.2@46.095,9.688
NetLD6_3: LD6.3 R27.2 | length 2.8
  Top Layer w0.2: R27.2@47.045,9.688 47.045,8.855 47.27,8.63 LD6.3@47.27,7
NetQ1_1: Q1.1 R16.1 R17.2 R20.2 | length 3.3
  Top Layer w0.2: R17.2@53.75,15.159 R20.2@54.69,15.159 ; R16.1@54.69,16.044 R20.2@54.69,15.159 ; Q1.1@55.05,13.8 55.05,14.54 54.69,14.9 R20.2@54.69,15.159
NetQ1_2: Q1.2 R21.2 | length 3.6
  Top Layer w0.2: v1(52.025,11.471) 52.025,11.536 53.15,12.661 Q1.2@53.15,13.8
  Bottom Layer w0.2: R21.2@52.025,10.7 v1(52.025,11.471)
NetR1_1: R1.1 R5.1 U13.A1 | length 10.1
  Top Layer w0.25: U13.A1@22.339,50.761 22.339,51.25
  Top Layer w0.49: 22.339,51.25 cw(c23.437,51.134) 23.149,52.2 29.262,52.2 ; 29.304,52.206 ccw(c28.759,53.957) 30.469,53.295 30.469,53.834
NetR7_2: R7.2 SB11.1 | length 0.9
  Bottom Layer w0.2: SB11.1@18.05,3.09 R7.2@18.99,3.09
NetR14_1: R14.1 SB28.2 | length 1.3
  Top Layer w0.3: R14.1@55.198,17.759 SB28.2@55.198,19.094
NetR18_1: R18.1 U8.2 | length 3.2
  Top Layer w0.2: U8.2@48.845,20.544 48.845,21.156 49.489,21.8 50.276,21.8 R18.1@50.913,22.438
NetR19_1: R19.1 U8.44 | length 1.5
  Top Layer w0.2: U8.44@50.845,17.044 52.288,17.044 R19.1@52.294,17.05
NetR22_1: R22.1 U8.3 | length 2.8
  Top Layer w0.2: U8.3@48.345,20.544 48.345,21.226 49.557,22.438 R22.1@49.913,22.438
NetR30_2: R30.2 SB32.1 U8.21 | length 3.5
  Top Layer w0.2: SB32.1@40.15,15.66 40.112,15.622 R30.2@40.112,14.6 40.998,14.6 41.442,15.044 U8.21@42.345,15.044
NetSB14_2: SB14.2 SB16.2 SW5.1 | length 40.3
  Top Layer w0.5: v1(47.6,30.961) 52.746,30.961 54.994,33.21 54.994,37.265 54.56,37.7 54.56,40.224 54.231,40.553 54.231,40.642 54.191,40.682 SB14.2@54.191,41.216
  VCC w0.7: v1(36.22,27.72) 36.22,26.37 38.89,23.7 v1(38.89,23.42)
  Bottom Layer w0.7: SB16.2@35.1,28.2 35.58,27.72 v1(36.22,27.72) 37.34,27.72
  Bottom Layer w0.8: SW5.1@36.327,20.565 36.825,20.565 37.64,21.38 37.64,22.17 v1(38.89,23.42) ; 37.34,27.72 40.581,30.961 v1(47.6,30.961)
NetU1_21: U1.21 U13.A3 | length 1.5
  Top Layer w0.2: U13.A3@22.339,49.587 U13.A3@22.339,49.613
  Top Layer w0.265: U1.21@22.339,48.087 U13.A3@22.339,49.587
NetU1_24: U1.24 X1.3 | length 3.3
  Top Layer w0.2: X1.3@19.002,50.529 19.213,50.529 19.674,50.068 19.674,49.295 20.839,48.13 U1.24@20.839,48.087
NetU1_25: U1.25 X1.1 | length 4.2
  Top Layer w0.2: X1.1@17.652,49.479 17.947,49.183 17.947,48.926 18.454,48.419 19.034,48.419 19.318,48.702 19.716,48.702 20.214,48.204 U1.25@20.214,47.462
NRST: B4.1 B4.3 CN6.3 CN7.14 D1.2 JP5.3 | length 96.3
  Top Layer w0.2: CN6.3@11.12,35.98 9.79,34.65 9.79,30.21 10.4,29.6 11.85,29.6 13.739,27.711 19.813,27.711 24.462,23.062 JP5.3@24.462,23.027 ; JP5.3@24.497,23.027 25.8,21.724 25.8,7.2 26.528,6.472 30.798,6.472 32.668,4.602 32.668,2.662 33.354,1.976 33.354,1.8 B4.1@33.454,1.9 34.09,1.9 34.53,2.34 36.65,2.34 37.09,1.9 B4.3@37.554,1.9 ; v1(33.9,33.44) 33.9,34.746 33.904,34.75 33.904,37.025 34.303,37.424 34.303,41.561 34.67,41.928 34.67,43.105 v1(34.657,43.117)
  Bottom Layer w0.2: CN7.14@6.04,35.98 CN6.3@11.12,35.98 ; JP5.3@24.497,23.027 23.086,24.438 23.086,31.186 23.4,31.5 25.516,31.5 26.317,32.301 26.319,32.301 26.319,32.665 26.318,32.666 26.318,32.916 26.323,32.922 26.323,33.003 27.172,33.852 29.094,33.852 29.096,33.85 29.181,33.85 29.63,33.4 29.857,33.4 29.859,33.398 30.191,33.398 30.193,33.4 33.86,33.4 v1(33.9,33.44) ; D1.2@31.769,45.421 32.595,44.595 32.595,44.335 33.457,43.473 34.302,43.473 v1(34.657,43.117)
PA0: CN7.34 CN8.4 SB11.2 U1.9 | length 63.7
  Top Layer w0.2: CN7.34@6.04,10.58 CN8.4@11.12,10.58 11.18,10.58 16.327,15.727 v1(16.327,24.5) ; U1.9@26.964,45.962 27.91,45.962 28.448,46.5 v1(28.6,46.5)
  Bottom Layer w0.2: CN8.4@11.12,10.58 12.77,8.93 12.77,5.98 15.66,3.09 SB11.2@17.075,3.09 ; v1(16.327,24.5) 17.625,25.798 17.625,35.685 21.647,39.706 25.332,39.706 26.803,41.177 26.803,45.827 27.176,46.2 28.3,46.2 v1(28.6,46.5)
PA1: CN7.32 CN8.3 U1.10 | length 52.5
  Top Layer w0.2: CN7.32@6.04,13.12 CN8.3@11.12,13.12 11.774,13.12 15.8,17.146 15.8,17.718 v1(15.8,23.7) ; U1.10@26.964,46.462 27.704,46.462 28.242,47 28.242,47.694 v1(27.906,48.03)
  Bottom Layer w0.2: v1(15.8,23.7) 15.8,29.282 16.337,29.819 16.337,36.125 21.127,40.916 24.752,40.916 25.5,41.664 25.5,46.298 27.232,48.03 v1(27.906,48.03)
PA2: CN7.36 CN8.5 U1.11 | length 54.9
  Top Layer w0.2: CN7.36@6.04,8.04 CN8.5@11.12,8.04 16.854,13.774 16.854,24.955 v1(16.327,25.482) ; U1.11@26.964,46.962 27.358,46.962 v1(27.666,47.27)
  Bottom Layer w0.2: v1(16.327,25.482) 16.327,29.147 16.772,29.592 16.772,35.972 16.79,35.99 21.135,40.335 21.313,40.513 24.919,40.513 25.95,41.544 25.95,46.154 27.067,47.27 v1(27.666,47.27)
PA3: CN7.38 CN8.6 U1.12 | length 60.8
  Top Layer w0.2: CN7.38@6.04,5.5 CN8.6@11.12,5.5 17.257,11.637 17.257,25.793 v1(16.95,26.1) ; U1.12@26.964,47.462 26.964,48 27.597,48.633 28.241,48.633 v1(28.787,48.087)
  Bottom Layer w0.2: v1(16.95,26.1) 16.95,29.2 17.175,29.425 17.175,35.805 21.48,40.11 25.126,40.11 26.4,41.384 26.4,46 27.018,46.618 27.918,46.618 28.787,47.487 v1(28.787,48.087)
PA4: CN7.28 CN8.1 U1.13 | length 47.4
  Top Layer w0.2: CN7.28@6.04,18.2 CN8.1@11.12,18.2 14.675,21.755 v1(14.675,23.7) ; U1.13@26.339,48.087 26.339,48.263 26.906,48.829 26.935,48.8 v1(26.989,48.8)
  Bottom Layer w0.2: v1(14.675,23.7) 14.675,29.365 15.53,30.22 15.53,36.343 20.852,41.665 24.249,41.665 24.597,42.012 24.597,48.742 25.482,49.627 26.199,49.627 26.989,48.837 v1(26.989,48.8)
PA5: CN5.6 CN10.11 U1.14 | length 47.7
  Top Layer w0.2: U1.14@25.839,48.087 25.839,48.333 26.462,48.956 26.462,49.068 26.738,49.344 30.313,49.344 35.61,44.047 35.61,40.318 v1(35.245,39.953)
  Bottom Layer w0.2: v1(35.245,39.953) 38.622,39.953 38.827,40.158 39.996,40.158 40.689,39.466 55.279,39.466 56.254,40.441 58.983,40.441 CN5.6@59.38,40.044 61.966,40.044 63.49,38.52 CN10.11@64.46,38.52
PA6: CN7.30 CN8.2 R9.2 U1.15 | length 75.8
  Top Layer w0.2: CN7.30@6.04,15.66 CN8.2@11.12,15.66 11.836,15.66 15.221,19.045 v1(15.221,24.53) ; U1.15@25.339,48.087 25.339,48.41 25.7,48.771 v1(25.7,49.062)
  Bottom Layer w0.2: CN8.2@11.12,15.66 13.777,13.003 13.777,7.145 14.682,6.24 25.232,6.24 26.051,5.421 26.682,5.421 29.075,3.029 R9.2@30.076,3.029 ; v1(15.221,24.53) 15.221,29.273 15.933,29.986 15.933,36.292 20.96,41.319 24.559,41.319 25,41.76 25,48.362 v1(25.7,49.062)
PA7: CN5.4 CN10.15 U1.16 | length 51.1
  Top Layer w0.2: U1.16@24.839,48.087 24.839,48.336 25.243,48.74 25.243,49.192 25.697,49.646 30.654,49.646 36.014,44.286 36.014,39.214 v1(35.642,38.843)
  Bottom Layer w0.2: v1(35.642,38.843) 35.657,38.858 38.79,38.858 39.045,38.603 55.677,38.603 59.316,34.964 CN5.4@59.38,34.964 61.708,34.964 63.232,33.44 CN10.15@64.46,33.44
PA8: CN9.7 CN10.25 U1.17 | length 67.1
  Top Layer w0.2: U1.17@24.339,48.087 24.339,48.4 24.907,48.967 24.907,49.334 25.529,49.957 30.993,49.957 36.417,44.533 36.417,39.045 36.22,38.848 36.22,38.42 v1(34.6,36.8)
  Bottom Layer w0.2: v1(34.6,36.8) 35.505,36.8 35.742,36.563 54.79,36.563 56.587,34.766 56.587,23.533 CN9.7@59.38,20.74 CN10.25@64.46,20.74
PA9: CN10.12 JP5.13 U1.18 | length 145.8
  Top Layer w0.2: U1.18@23.839,48.087 23.839,48.362 24.595,49.118 24.595,49.494 25.367,50.266 31.286,50.266 35.915,45.637 35.915,45.631 36.234,45.312 36.82,44.727 36.82,38.697 36.623,38.5 36.623,38.246 35.292,36.915 35.292,34.004 v1(34.87,33.583) ; v1(48.383,5.95) 49.036,5.297 49.918,5.297 51.115,4.1 55.1,4.1 56.3,5.3 57.838,5.3 58.132,5.006 58.132,4.337 58.269,4.2 60.4,4.2 60.681,4.481 60.681,6.443 63.457,9.22 67.52,9.22 68.75,10.45 68.75,36.77 CN10.12@67,38.52
  Bottom Layer w0.2: JP5.13@24.497,10.327 25.759,11.589 25.759,30.866 25.75,30.875 25.75,31.206 25.759,31.215 25.759,31.316 26.442,31.999 26.444,31.999 26.621,32.176 26.621,32.79 26.619,32.791 27.351,33.523 28.971,33.523 29.487,33.006 33.666,33.006 33.811,32.862 34.081,32.862 34.313,33.094 34.313,33.287 34.608,33.583 v1(34.87,33.583) ; JP5.13@24.503,10.3 25.7,9.103 25.7,7.26 26.525,6.435 27.053,6.435 28.248,5.24 34.59,5.24 37.208,2.622 43.922,2.622 46.5,5.2 46.5,5.433 47.017,5.95 v1(48.383,5.95)
PA10: CN10.14 JP5.15 U1.36 | length 114.3
  Top Layer w0.2: v1(19.664,34.251) 18.775,35.14 18.775,39.499 20.214,40.938 U1.36@20.214,41.962 ; v1(49.165,5.95) 49.415,5.7 50.1,5.7 51.27,4.53 54.906,4.53 56.106,5.73 57.708,5.73 57.943,5.965 57.943,6.477 58.098,6.632 60.238,6.632 60.387,6.78 63.271,9.665 63.271,11.516 63.655,11.9 67.6,11.9 68.34,12.64 68.34,34.64 CN10.14@67,35.98
  Bottom Layer w0.2: v1(19.664,34.251) 19.427,34.014 19.427,12.857 JP5.15@24.497,7.787 ; JP5.15@24.503,7.81 26.346,5.966 26.879,5.966 28.015,4.83 34.404,4.83 37.034,2.2 44.126,2.2 46.626,4.7 47.915,4.7 v1(49.165,5.95)
PA11: CN9.6 CN10.27 U1.37 | length 69.1
  Top Layer w0.2: U1.37@20.839,41.337 20.839,40.99 19.197,39.348 19.197,35.665 21.762,33.1 v1(23.65,33.1)
  Bottom Layer w0.2: v1(23.65,33.1) 23.803,33.1 25.925,35.222 28.188,35.222 28.98,36.014 33.602,36.014 33.748,36.16 54.623,36.16 56.122,34.661 56.122,21.458 CN9.6@59.38,18.2 CN10.27@64.46,18.2
PA12: CN9.4 CN10.31 U1.38 | length 74.7
  Top Layer w0.2: U1.38@21.339,41.337 21.339,40.916 19.6,39.178 19.6,35.862 22.016,33.446 23.334,33.446 23.435,33.546 23.843,33.546 23.943,33.446 24.518,33.446 v1(25.346,32.617)
  Bottom Layer w0.2: v1(25.346,32.617) 25.346,33.216 26.612,34.482 28.4,34.482 28.454,34.536 28.459,34.536 29.13,35.207 33.936,35.207 34.082,35.354 54.289,35.354 55.315,34.327 55.315,20.09 56.062,19.343 56.062,17.706 55.555,17.199 55.555,15.17 57.605,13.12 CN9.4@59.38,13.12 CN10.31@64.46,13.12
PA13: CN7.13 JP5.5 U1.39 | length 57.8
  Top Layer w0.2: CN7.13@3.5,35.98 4.72,34.76 6.55,34.76 7.4,33.91 7.4,29.41 9.698,27.112 12.117,27.112 12.37,27.365 19.435,27.365 23.339,23.461 23.339,22.483 23.7,22.122 23.7,21.284 JP5.5@24.497,20.487 ; U1.39@21.839,41.337 21.839,40.846 20.006,39.014 20.006,36.292 v1(22.137,34.161)
  Bottom Layer w0.2: v1(22.137,34.161) 21.791,34.161 20.637,33.006 20.637,21.603 21.753,20.487 JP5.5@24.497,20.487
PA14: CN7.15 JP5.7 U1.41 | length 63.8
  Top Layer w0.2: CN7.15@3.5,33.44 3.5,33.3 4.669,32.131 4.669,25.562 5.563,24.668 11.832,24.668 14.19,27.026 19.204,27.026 23.012,23.217 23.012,22.352 23.304,22.06 23.304,19.927 23.844,19.387 24.25,19.387 24.497,19.14 JP5.7@24.497,17.947 ; U1.41@22.839,41.337 22.839,40.275 23.897,39.217 23.897,37.497 v1(23.7,37.3)
  Bottom Layer w0.2: v1(23.7,37.3) 23.7,36.633 20.233,33.166 20.233,20.567 22.854,17.947 JP5.7@24.497,17.947
PA15: CN5.2 CN10.19 U1.42 | length 50.9
  Top Layer w0.2: U1.42@23.339,41.337 23.339,40.345 24.3,39.384 24.3,38.46 24.921,37.839 v1(24.921,37.494)
  Bottom Layer w0.2: v1(24.921,37.494) 25.152,37.263 26.517,37.263 26.593,37.339 32.995,37.339 33.805,38.148 35.868,38.148 36.243,37.773 55.357,37.773 57.797,35.333 57.797,31.403 59.316,29.884 CN5.2@59.38,29.884 61.156,29.884 62.68,28.36 CN10.19@64.46,28.36
PB0: CN9.3 CN10.33 R3.1 SB5.1 U1.28 | length 113.7
  Top Layer w0.2: v1(14.9,31.7) 14.925,31.725 21.213,31.725 v1(22.309,30.629) ; SB5.1@17.801,47.447 17.801,47.35 18.038,47.113 18.692,47.113 19.149,46.655 19.149,46.259 19.433,45.974 v1(19.812,45.974) ; v1(49.045,8.4) 49.232,8.213 50.537,8.213 51.007,8.682 51.007,8.684 51.126,8.803 57.603,8.803 CN9.3@59.38,10.58
  Bottom Layer w0.2: v1(14.9,31.7) 15.09,31.89 15.09,36.79 17.729,39.429 17.729,42.749 18.295,43.315 18.807,43.315 19.24,43.748 19.24,44.978 19.362,45.1 19.362,45.786 19.55,45.974 v1(19.812,45.974) ; v1(22.309,30.629) 22.309,31.034 23.241,31.966 25.466,31.966 25.9,32.4 25.9,33.17 26.869,34.139 27.033,34.139 27.047,34.153 28.57,34.153 29.221,34.804 34.113,34.804 34.259,34.951 54.122,34.951 54.912,34.16 54.912,19.877 55.659,19.13 55.659,17.873 55.151,17.366 55.151,14.999 59.38,10.77 CN9.3@59.38,10.58 CN10.33@64.46,10.58 ; R3.1@41.631,5.939 42.391,6.699 44.837,6.699 46.538,8.4 v1(49.045,8.4)
PB1: CN9.5 CN10.29 R4.1 SB6.1 U1.29 | length 115.2
  Top Layer w0.2: v1(14.8,30.255) 15.259,29.796 v1(22.3,29.796) ; SB6.1@17.773,46.38 17.778,46.375 v1(18.542,46.375) 18.542,46.346 18.822,46.066 18.895,46.066 19.465,45.496 19.795,45.496 19.829,45.462 U1.29@20.214,45.462 ; v1(50.48,8.9) 50.786,9.206 57.409,9.206 58.003,9.8 58.003,14.283 CN9.5@59.38,15.66
  Bottom Layer w0.2: v1(14.8,30.255) 14.8,31.055 14.373,31.482 14.373,32.01 14.687,32.324 14.687,36.815 17.385,39.514 17.385,39.516 17.42,39.551 17.42,42.94 18.367,43.886 18.367,44.669 18.954,45.256 18.954,45.963 v1(18.542,46.375) ; v1(22.3,29.796) 21.752,30.344 21.752,31.156 23.054,32.458 23.899,32.458 26.325,34.884 28.379,34.884 28.377,34.886 28.515,35.024 28.517,35.024 29.104,35.611 33.769,35.611 33.915,35.757 54.456,35.757 55.718,34.494 55.718,20.344 56.587,19.475 56.587,18.513 59.38,15.72 CN9.5@59.38,15.66 CN10.29@64.46,15.66 ; R4.1@43.124,5.939 43.455,6.27 44.991,6.27 46.508,7.787 49.367,7.787 v1(50.48,8.9)
PB2: CN5.3 CN10.17 U1.19 | length 55.7
  Top Layer w0.15: U1.19@23.339,48.087 23.339,48.29 23.53,48.481 23.53,48.583
  Top Layer w0.2: 23.53,48.583 24.206,49.26 24.206,49.584 25.21,50.588 31.534,50.588 36.363,45.76 36.36,45.757 37.223,44.894 37.223,38.314 v1(37.209,38.3)
  Bottom Layer w0.2: v1(37.209,38.3) 37.309,38.2 55.5,38.2 58.2,35.5 58.2,33.534 59.31,32.424 CN5.3@59.38,32.424 61.691,32.424 63.215,30.9 CN10.17@64.46,30.9
PB3: CN10.30 JP5.9 U1.43 | length 98
  Top Layer w0.2: U1.43@23.839,41.337 23.839,40.416 24.703,39.551 24.703,38.697 25.451,37.95 25.451,37.457 26.107,36.8 v1@26.785,36.8 ; JP5.9@24.497,15.407 23.1,14.01 23.1,6.786 24.066,5.82 v1(28.63,5.82) ; v1(48.6,7) 48.67,7 49.457,7.787 50.787,7.787 51.4,8.4 57.9,8.4 58.8,9.3 61.6,9.3 62.2,9.9 62.2,12.7 63.904,14.404 65.744,14.404 CN10.30@67,15.66
  Bottom Layer w0.2: JP5.9@24.497,15.407 19.83,20.074 19.83,33.432 23,36.602 23,37.341 23.173,37.514 23.173,37.518 23.482,37.827 23.961,37.827 24.307,37.481 24.307,37.299 24.821,36.785 v1(26.785,36.785) ; v1(28.63,5.82) 28.709,5.741 34.659,5.741 37.375,3.025 43.685,3.025 45.08,4.42 45.08,5.38 46.7,7 v1(48.6,7)
PB4: CN5.5 CN10.13 U1.44 | length 45.2
  Top Layer w0.2: U1.44@24.339,41.337 24.339,40.486 25.179,39.646 25.179,38.792 26.029,37.942 v1(26.029,37.7)
  Bottom Layer w0.2: v1(26.029,37.7) 26.071,37.742 26.419,37.742 26.434,37.727 30.923,37.727 30.938,37.742 32.489,37.742 34.131,39.384 38.623,39.384 38.994,39.755 39.829,39.755 40.522,39.062 57.822,39.062 CN5.5@59.38,37.504 61.826,37.504 63.35,35.98 CN10.13@64.46,35.98
PB5: CN5.1 CN10.21 R2.1 U1.45 | length 88.9
  Top Layer w0.2: U1.45@24.839,41.337 24.839,40.612 25.665,39.786 25.665,38.9 27.6,36.965 v1(27.6,36.6) ; v1(48.6,9) 49.8,9 50.143,9.343 50.41,9.61 57.242,9.61 57.6,9.967 57.6,25.564 CN5.1@59.38,27.344
  Bottom Layer w0.2: v1(27.6,36.6) 27.89,36.89 33.19,36.89 34.03,37.73 35.716,37.73 36.076,37.37 55.124,37.37 57.394,35.1 57.394,29.33 CN5.1@59.38,27.344 60.936,27.344 62.46,25.82 CN10.21@64.46,25.82 ; R2.1@40,5.939 41.161,7.1 44.656,7.1 46.555,9 v1(48.6,9)
PB6: CN9.2 CN10.35 U1.46 | length 69.3
  Top Layer w0.2: U1.46@25.339,41.337 25.339,40.717 26.141,39.915 26.141,39.027 29.262,35.906 v1(29.262,34.251)
  Bottom Layer w0.2: v1(29.262,34.251) 29.412,34.401 34.28,34.401 34.426,34.547 53.853,34.547 54.425,33.975 54.425,19.775 55.256,18.944 55.256,18.04 54.748,17.533 54.748,14.742 57,12.49 57,11 56.29,10.29 56.29,9.51 57.76,8.04 CN9.2@59.38,8.04 CN10.35@64.46,8.04
PB7: CN9.1 CN10.37 U1.47 | length 69.6
  Top Layer w0.2: U1.47@25.839,41.337 25.839,40.788 26.621,40.005 26.621,38.993 27.1,38.514 27.254,38.514 30.025,35.743 v1(30.025,33.8)
  Bottom Layer w0.2: v1(30.025,33.8) 30.011,33.8 30.209,33.998 34.447,33.998 34.593,34.144 52.477,34.144 54,32.621 54,19.57 54.853,18.718 54.853,18.207 54.345,17.7 54.345,14.41 56.597,12.158 56.597,11.167 55.887,10.457 55.887,8.993 CN9.1@59.38,5.5 CN10.37@64.46,5.5
PB8: CN5.10 CN10.3 U1.5 | length 42.4
  Top Layer w0.2: U1.5@26.964,43.962 27.315,43.962 27.412,44.059 29.399,44.059 30.399,45.059 31.741,45.059 32.1,44.7 33.347,44.7 v1(33.559,44.488)
  Bottom Layer w0.2: v1(33.559,44.488) 33.559,45.107 35.845,47.393 35.845,48.798 36.725,49.678 41.386,49.678 41.912,50.204 CN5.10@59.38,50.204 59.43,50.204 60.954,48.68 CN10.3@64.46,48.68
PB9: CN5.9 CN10.5 U1.6 | length 44.3
  Top Layer w0.2: U1.6@26.964,44.462 29.232,44.462 30.232,45.462 31.908,45.462 32.225,45.146 33.749,45.146 34.27,44.625 v1(34.27,44)
  Bottom Layer w0.2: v1(34.27,44) 34.27,45.221 36.363,47.314 36.363,48.746 36.892,49.275 41.628,49.275 42.127,49.773 57.271,49.773 CN5.9@59.38,47.664 59.436,47.664 60.96,46.14 CN10.5@64.46,46.14
PC14: CN7.25 SB10.1 | length 44.9
  Top Layer w0.2: v1(31.548,40.136) 31.548,40.875 31.558,40.885 SB10.1@31.552,40.891
  Bottom Layer w0.2: CN7.25@3.5,20.74 4.84,19.4 6.731,19.4 7.531,20.2 14.075,20.2 18.515,24.64 18.515,35.415 22,38.9 26.46,38.9 26.846,38.514 30.489,38.514 31.548,39.573 v1(31.548,40.136)
PC15: CN7.27 SB12.1 | length 52.4
  Top Layer w0.2: SB12.1@31.552,43.679 v1(31.552,44.419)
  Bottom Layer w0.2: CN7.27@3.5,18.2 2.23,19.47 2.23,21.305 2.925,22 6.6,22 7.871,20.729 13.904,20.729 18.09,24.915 18.09,35.563 21.83,39.303 25.501,39.303 27.25,41.052 27.248,41.053 27.248,43.838 27.534,44.124 28.787,44.124 29.011,43.9 31.06,43.9 31.552,44.393 v1(31.552,44.419)
PE4: CN9.8 CN10.23 R8.2 U1.30 | length 112.7
  Top Layer w0.2: v1(14.1,30.955) 14.935,30.955 15.385,30.505 v1(21.2,30.505) ; v1(17.769,45.705) 17.828,45.764 18.77,45.764 19.34,45.194 19.67,45.194 19.78,45.084 19.782,45.084 19.904,44.962 U1.30@20.214,44.962 ; v1(21.595,22.05) 21.595,5.717 v1(23.3,4.012)
  Bottom Layer w0.2: v1(14.1,30.955) 13.9,31.155 13.9,32.206 14.284,32.59 14.284,36.839 17.084,39.639 17.084,43.046 17.975,43.936 17.975,45.499 v1(17.769,45.705) ; v1(21.595,22.05) 21.189,22.456 21.2,22.467 v1(21.2,30.505) 21.2,31.233 25.516,35.549 28.006,35.549 28.943,36.487 33.422,36.487 34.263,37.327 35.549,37.327 35.909,36.967 54.957,36.967 56.99,34.933 56.99,25.731 59.38,23.341 CN9.8@59.38,23.28 CN10.23@64.46,23.28 ; v1(23.3,4.012) R8.2@24.15,4.012
PWR_ENn: R11.1 U4.4 U8.28 | length 26.9
  Top Layer w0.2: U8.28@45.345,12.044 v1(45.345,15.2) ; v1(48.966,32.884) 48.966,34.849 R11.1@49.165,35.048 49.165,35.765 49.814,36.414 U4.4@49.814,36.854
  Bottom Layer w0.2: v1(45.345,15.2) 45.345,17.702 47.214,19.571 47.214,23.557 47.468,23.811 47.468,23.818 47.777,24.127 47.784,24.127 49.223,25.566 49.223,32.627 v1(48.966,32.884)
